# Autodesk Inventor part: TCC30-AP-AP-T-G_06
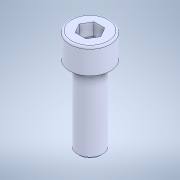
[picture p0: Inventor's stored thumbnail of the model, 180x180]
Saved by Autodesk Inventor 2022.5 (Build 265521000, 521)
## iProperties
Created: 2023-09
Part Number: TCC30-AP-AP-T-G_06
Material: 一般
Document SubType Name: Modeling
Designer: ImaoCorp
Density: 1 g/cm^3
Appearance: 既定
Author: ImaoCorp
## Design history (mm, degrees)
feature "TCC30-AP-AP-T-G_06"
node "ソリッド1"
